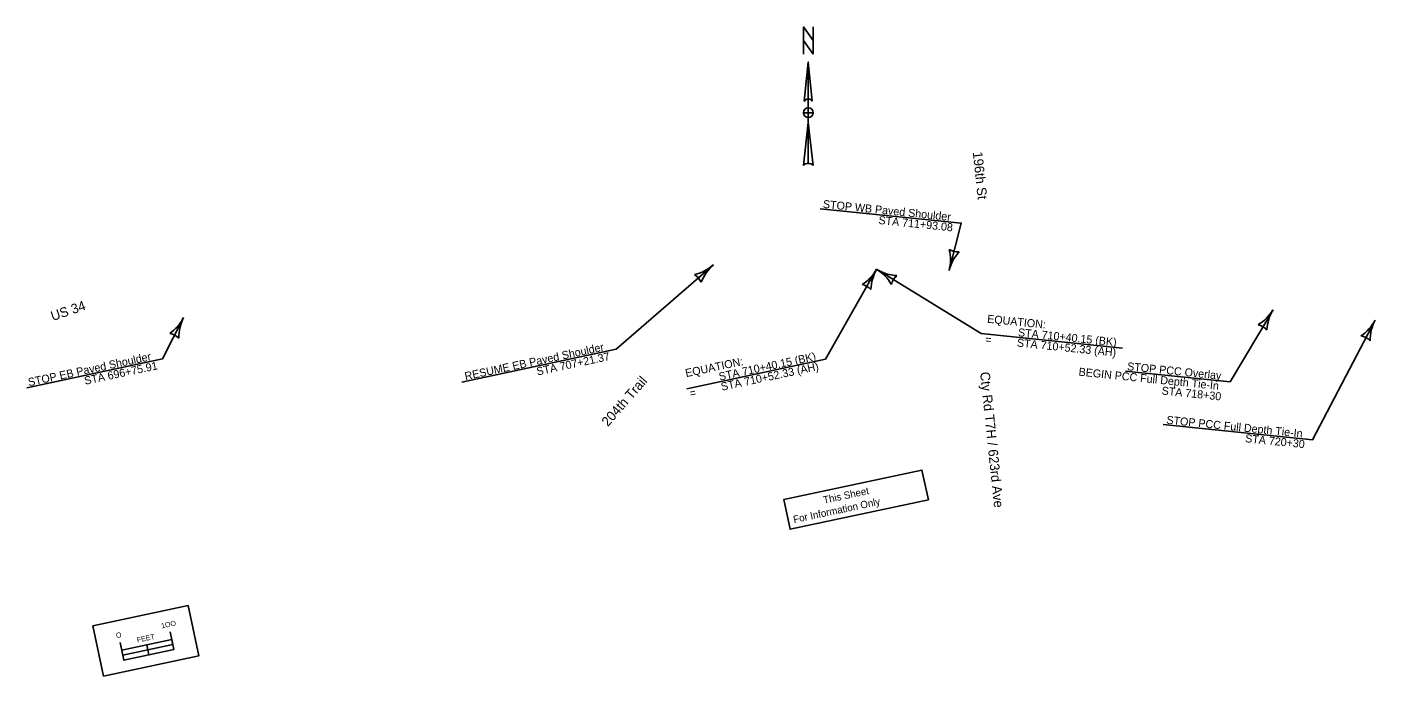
# Model space of a CAD drawing. Extents: x 22712865 to 22760106, y 6235088 to 6238602.
# Drawn here: x 22746496 to 22749125, y 6237336 to 6238602 of the extents above; entities that cross this region are included whole.
import ezdxf

# ---------------------------------------------------------------- set-up
doc = ezdxf.new("R2010")
doc.units = 0
for name, color, linetype in [('_CIVIL_CONSTRUCTION', 7, 'Continuous'), ('Default', 7, 'Continuous'), ('Draft_3', 7, 'Continuous'), ('dsnTextOdd', 7, 'Continuous'), ('Entrance', 7, 'Continuous')]:
    doc.layers.add(name, color=color, linetype=linetype)

msp = doc.modelspace()

# ---------------------------------------------------------------- linework, layer by layer
at = {"layer": '_CIVIL_CONSTRUCTION'}
msp.add_line((22746734.3, 6237377.6), (22746730.1, 6237397.2), dxfattribs=at)
msp.add_line((22746734.3, 6237377.6), (22746730.1, 6237397.2), dxfattribs=at)
for points in [[(22746625.1, 6237434.1), (22746810.9, 6237473.8), (22746831.8, 6237376), (22746645.9, 6237336.3)], [(22746645.9, 6237336.3), (22746625.1, 6237434.1), (22746810.9, 6237473.8), (22746831.8, 6237376)], [(22746732.1, 6237387.5), (22746781, 6237397.9), (22746779, 6237407.6), (22746730.1, 6237397.2)], [(22746685.4, 6237367.2), (22746734.3, 6237377.6), (22746732.1, 6237387.5), (22746683.3, 6237377)]]:
    msp.add_lwpolyline(points, close=True, dxfattribs=at)
for points in [[(22746678, 6237401.4), (22746685.4, 6237367.2), (22746783.1, 6237388.1), (22746775.8, 6237422.3)], [(22746681.2, 6237386.8), (22746779, 6237407.6)]]:
    msp.add_lwpolyline(points, dxfattribs=at)
at = {"layer": 'Draft_3'}
for points in [[(22747834.7, 6238138.1), (22747645.4, 6237973.6), (22747344.6, 6237909.4)], [(22746801.9, 6238035.7), (22746760.9, 6237954.8), (22746496.4, 6237898.4)], [(22748925.9, 6238050.8), (22748842.2, 6237910.2), (22748638.6, 6237931)], [(22749124.8, 6238030.4), (22749003, 6237797.1), (22748711.8, 6237826.8)]]:
    msp.add_lwpolyline(points, dxfattribs=at)
for centre, radius, start, end in [((22747778.9, 6238202.3), 85, 282.9191, 310.9916), ((22747890.5, 6238073.9), 85, 130.9916, 159.0641), ((22747780.9, 6238091.3), 32.8, 23.2582, 58.7249), ((22746726.1, 6238074.1), 85, 305.0064, 333.0789), ((22746877.7, 6237997.2), 85, 153.0789, 181.1514), ((22748852.8, 6238094.2), 85, 301.1592, 329.2317), ((22748998.9, 6238007.3), 85, 149.2317, 177.3042), ((22749049.5, 6238069.8), 85, 304.3514, 332.4239), ((22749200.2, 6237991.1), 85, 152.4239, 180.4964), ((22746769.7, 6237972.1), 32.8, 45.3456, 80.8123), ((22748889.4, 6237989.5), 32.8, 41.4984, 76.9651), ((22749091.8, 6237967.3), 32.8, 44.6905, 80.1572)]:
    msp.add_arc(centre, radius, start, end, dxfattribs=at)
at = {"layer": 'dsnTextOdd'}
for points in [[(22748294.3, 6238127.3), (22748318.2, 6238219.7), (22748043, 6238247.8)], [(22748153.1, 6238129.7), (22748356.9, 6238004.2), (22748632.3, 6237976)]]:
    msp.add_lwpolyline(points, dxfattribs=at)
for centre, radius, start, end in [((22748212, 6238148.6), 85, 345.4906, 13.5631), ((22748376.6, 6238106), 85, 137.4181, 165.4906), ((22748312.2, 6238196.3), 32.8, 237.7573, 273.224), ((22748108.5, 6238057.3), 85, 30.297, 58.3694), ((22748197.7, 6238202.1), 85, 238.3694, 266.4419), ((22748213.8, 6238092.3), 32.8, 130.6361, 166.1028)]:
    msp.add_arc(centre, radius, start, end, dxfattribs=at)
at = {"layer": 'Entrance'}
for p, q in [((22748019.8, 6238533.9), (22748027.4, 6238457.8)), ((22748019.8, 6238533.9), (22748019.8, 6238336.1)), ((22748012.2, 6238457.8), (22748012.1, 6238457.8)), ((22748012.4, 6238458.5), (22748013.9, 6238460.1)), ((22748019.8, 6238425.5), (22748019.8, 6238425.5)), ((22748010.2, 6238332.3), (22748019.8, 6238416))]:
    msp.add_line(p, q, dxfattribs=at)
for points in [[(22748029.3, 6238549.1), (22748010.2, 6238575.7), (22748010.2, 6238602.3), (22748029.3, 6238575.7)], [(22747984.3, 6237622.6), (22748253.9, 6237680.2), (22748241.5, 6237737.9), (22747972, 6237680.4)], [(22747972, 6237680.4), (22748241.5, 6237737.9), (22748253.9, 6237680.2), (22747984.3, 6237622.6)]]:
    msp.add_lwpolyline(points, close=True, dxfattribs=at)
for points in [[(22748010.2, 6238549.1), (22748010.2, 6238602.3), (22748029.3, 6238575.7), (22748029.3, 6238602.3)], [(22748012.1, 6238457.8), (22748019.8, 6238533.9), (22748019.8, 6238461.6)], [(22748019.8, 6238425.5), (22748019.8, 6238435), (22748010.2, 6238435)], [(22748029.3, 6238435), (22748019.8, 6238435), (22748019.8, 6238444.5)], [(22748019.8, 6238336.1), (22748019.8, 6238416), (22748029.3, 6238332.3)], [(22748153.1, 6238129.7), (22748053.2, 6237954.1), (22747782.7, 6237896.3)]]:
    msp.add_lwpolyline(points, dxfattribs=at)
for centre, radius, start, end in [((22748019.8, 6238452.1), 9.51, 90.0204, 143.1257), ((22748019.8, 6238452.1), 9.5, 36.8481, 90.0218), ((22748019.8, 6238435), 9.51, 90, 180), ((22748019.8, 6238435), 9.51, 180, 270), ((22748019.8, 6238435), 9.51, 0, 90), ((22748019.8, 6238435), 9.51, 270, 360), ((22748019.8, 6238322.3), 13.8, 89.9894, 133.619), ((22748019.8, 6238322.3), 13.8, 46.4021, 90.0006), ((22748079.2, 6238171.7), 85, 302.2932, 330.3657), ((22748227, 6238087.7), 85, 150.3657, 178.4382), ((22748117.9, 6238067.7), 32.8, 42.6323, 78.099)]:
    msp.add_arc(centre, radius, start, end, dxfattribs=at)

# ---------------------------------------------------------------- texts
at = {"layer": '_CIVIL_CONSTRUCTION'}
for s, p in [('1OO', (22746759.2, 6237429)), ('1OO', (22746759.2, 6237429)), ('O', (22746671.1, 6237410.2)), ('O', (22746671.1, 6237410.2)), ('FEET', (22746711.8, 6237401.5))]:
    msp.add_text(s, height=10, rotation=12.0545, dxfattribs=at).set_placement(p)
at = {"layer": 'Default'}
for s, rotation, p in [('196th St', 275.9179, (22748340.6, 6238358.1)), ('US 34', 19.0497, (22746546.7, 6238028.6)), ('204th Trail', 48.8427, (22747629.1, 6237821.7)), ('Cty Rd T7H / 623rd Ave', 275.9179, (22748354.8, 6237928.6))]:
    msp.add_text(s, height=18.75, rotation=rotation, dxfattribs=at).set_placement(p)
at = {"layer": 'Draft_3'}
for s, height, rotation, p in [('RESUME EB Paved Shoulder', 15.601, 12.0545, (22747351.6, 6237913.2)), ('STOP EB Paved Shoulder', 15.601, 12.0545, (22746500.3, 6237901.5)), ('STA 696+75.91', 15.601, 12.0545, (22746610, 6237904.3)), ('STA 707+21.37', 15.601, 12.0545, (22747491.6, 6237922.4)), ('BEGIN PCC Full Depth Tie-In', 15.601, 354.1689, (22748546.3, 6237922.4)), ('STOP PCC Overlay', 15.601, 354.1689, (22748641, 6237933)), ('STA 718+30', 15.6, 354.1689, (22748708.2, 6237885.6)), ('STOP PCC Full Depth Tie-In', 15.601, 354.1689, (22748717.5, 6237828.5)), ('STA 720+30', 15.6, 354.1689, (22748871, 6237792.5))]:
    msp.add_text(s, height=height, rotation=rotation, dxfattribs=at).set_placement(p)
at = {"layer": 'dsnTextOdd'}
for s, height, p in [('STOP WB Paved Shoulder', 15.601, (22748047.8, 6238249.5)), ('STA 711+93.08', 15.601, (22748156.1, 6238218.2)), ('EQUATION:', 15.6, (22748368, 6238025.6)), ('STA 710+40.15 (BK)', 15.601, (22748428.1, 6237999.2)), ('=', 15.6, (22748363.9, 6237985.4)), ('STA 710+52.33 (AH)', 15.601, (22748426, 6237979.1))]:
    msp.add_text(s, height=height, rotation=354.1689, dxfattribs=at).set_placement(p)
at = {"layer": 'Entrance'}
for s, height, p in [('EQUATION:', 15.6, (22747781.8, 6237919.2)), ('STA 710+40.15 (BK)', 15.601, (22747847.1, 6237912.4)), ('STA 710+52.33 (AH)', 15.601, (22747851.3, 6237892.7)), ('=', 15.6, (22747790.2, 6237879.7)), ('This Sheet', 14.17, (22748050.5, 6237672.4)), ('For Information Only', 14.175, (22747992.1, 6237634.5))]:
    msp.add_text(s, height=height, rotation=12.0545, dxfattribs=at).set_placement(p)

doc.saveas('drawing.dxf')
